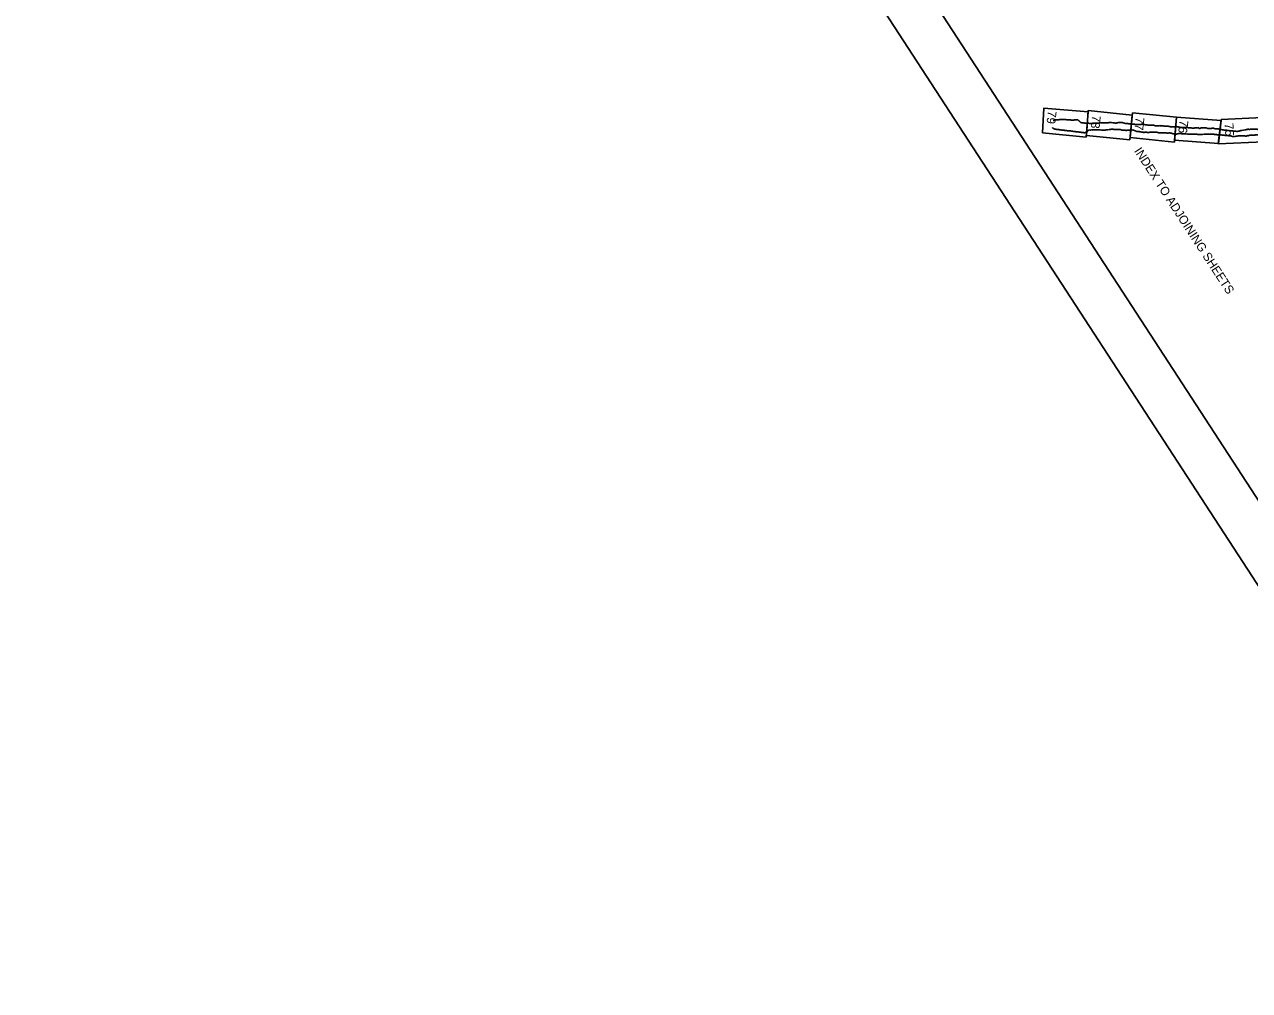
# Model space of a CAD drawing. Extents: x 3953924 to 3974542, y 193747 to 216192.
# Drawn here: x 3954169 to 3962352, y 193991 to 200444 of the extents above; entities that cross this region are included whole.
import ezdxf

# ---------------------------------------------------------------- set-up
doc = ezdxf.new("R2010")
doc.units = 0
for name, color, linetype in [('G-ANNO-NPLT', 7, 'Continuous'), ('V-ANNO-NPLT', 7, 'Continuous'), ('V-ANNO-SYMB', 7, 'Continuous')]:
    doc.layers.add(name, color=color, linetype=linetype)

msp = doc.modelspace()

# ---------------------------------------------------------------- linework, layer by layer
at = {"layer": 'G-ANNO-NPLT'}
msp.add_lwpolyline([(3954168.8, 209355.9), (3964170.5, 193991), (3974297.3, 200583), (3964295.6, 215947.9)], close=True, dxfattribs=at)
at = {"layer": 'V-ANNO-NPLT'}
msp.add_line((3961273.8, 199859.7), (3961261.8, 199692.1), dxfattribs=at)
for points in [[(3961273.8, 199859.7), (3960979.2, 199885.4), (3960970, 199720.3), (3961261.8, 199692.1)], [(3961568.2, 199838.9), (3961274.4, 199869.1), (3961262.6, 199703.3)], [(3961568.2, 199838.9), (3961553.6, 199673.4)], [(3961569.6, 199854.8), (3961555.1, 199689.7), (3961850.9, 199658.3)], [(3961865.6, 199824.2), (3961569.6, 199854.8)], [(3961850.9, 199658.3), (3961865.6, 199824.2)], [(3961865.6, 199824.2), (3961852, 199671.2)], [(3961865.6, 199824.2), (3962162.6, 199802.9)], [(3962163.5, 199810.2), (3962143.7, 199645.8), (3962448.5, 199660.1)], [(3962162.6, 199802.9), (3962144.2, 199649.7)], [(3962440.7, 199823.2), (3962163.5, 199810.2)], [(3961262.6, 199703.3), (3961553.6, 199673.4)], [(3961852, 199671.2), (3962144.2, 199649.7)]]:
    msp.add_lwpolyline(points, dxfattribs=at)
for points in [[(3961096.7, 199809.1), (3961085.3, 199808.5), (3961078.5, 199807.9), (3961071.7, 199807.5), (3961065.3, 199807.3), (3961059.1, 199806.8), (3961053.9, 199806.7), (3961052.5, 199806), (3961049.8, 199804.6), (3961045.7, 199802.6), (3961044.5, 199802), (3961043.2, 199802.1), (3961041.5, 199802.7)], [(3961149.7, 199806.4), (3961137.4, 199807.6), (3961124.6, 199808.3), (3961114.5, 199808.5), (3961106.8, 199809.1), (3961099.1, 199809.6), (3961096.7, 199809.1)], [(3961210.2, 199803.1), (3961205.6, 199806.2), (3961203.1, 199807), (3961197.3, 199806.6), (3961189.8, 199806.1), (3961183.1, 199805.9), (3961176.5, 199805.4), (3961171.3, 199805.2), (3961165.1, 199805.5), (3961155.8, 199806), (3961149.7, 199806.4)], [(3961268.1, 199784.4), (3961264.2, 199784.6), (3961258.9, 199785), (3961255.2, 199785.4), (3961250.7, 199785.6), (3961245.3, 199786.4), (3961238, 199787.1), (3961232.3, 199787.7), (3961228.4, 199788.2), (3961224.8, 199788.5), (3961220, 199793), (3961216.3, 199796.9), (3961213.7, 199799.8), (3961210.2, 199803.1)], [(3961289.4, 199783), (3961284.4, 199783.2), (3961279.6, 199783.7), (3961268.1, 199784.4)], [(3961430.7, 199788.8), (3961419, 199789.5), (3961407.3, 199787.3), (3961403.3, 199786.8), (3961391.6, 199787), (3961380.6, 199786.9), (3961369.7, 199787.2), (3961362.4, 199787.4), (3961357.5, 199788.3), (3961352.5, 199786.8), (3961329.4, 199785), (3961310.5, 199782.5), (3961300.4, 199781.9), (3961295.6, 199782.5), (3961289.4, 199783)], [(3961553, 199780.5), (3961539.9, 199781.5), (3961529.3, 199782.2), (3961522.7, 199783), (3961515.3, 199784.9), (3961500.9, 199789), (3961493.3, 199788.7), (3961482.2, 199789.5), (3961471, 199787.8), (3961461.7, 199785.7), (3961447.8, 199786.4), (3961430.7, 199788.8)], [(3961633.1, 199777.7), (3961626.8, 199776.6), (3961619.2, 199776.4), (3961610.6, 199776.3), (3961597.8, 199776.5), (3961575.1, 199778.2), (3961563, 199779.2), (3961552.8, 199780.6)], [(3961858.8, 199761.9), (3961850.7, 199761), (3961842.9, 199759.5), (3961835.1, 199760), (3961825, 199761.1), (3961814.2, 199763.2), (3961807.4, 199764.3), (3961788.8, 199764.8), (3961775.8, 199766.2), (3961762.3, 199767.2), (3961752.9, 199768.1), (3961744.8, 199767.1), (3961734, 199767), (3961722.5, 199768), (3961713.5, 199770.5), (3961701.3, 199771.6), (3961684.9, 199770.8), (3961681, 199771.7), (3961678.1, 199772), (3961666.2, 199772.6), (3961656.5, 199774), (3961643.7, 199776.2), (3961633.1, 199777.7)], [(3962002.3, 199752.9), (3961987, 199752.6), (3961976.1, 199751.9), (3961963.5, 199753), (3961950.7, 199753.2), (3961938.3, 199755.1), (3961918.9, 199756.3), (3961912.1, 199756.5), (3961902.6, 199755.1), (3961892, 199756.6), (3961880.1, 199758.9), (3961869.1, 199760.9), (3961858.8, 199761.9)], [(3961082.5, 199741.2), (3961074.9, 199742), (3961067.2, 199743), (3961060.2, 199743.9), (3961056, 199744.7), (3961050.8, 199745.5), (3961045.6, 199748), (3961040.5, 199750.6), (3961036.1, 199753.6), (3961033.3, 199755.9)], [(3961145.2, 199733.2), (3961135.3, 199734.5), (3961123, 199736.2), (3961114.6, 199737.3), (3961104.6, 199738.3), (3961092.4, 199739.9), (3961082.5, 199741.2)], [(3961213.8, 199725.4), (3961203.7, 199726.5), (3961197.1, 199727.2), (3961188.1, 199728.5), (3961179.7, 199729.2), (3961174.8, 199730), (3961168.3, 199730.8), (3961156.6, 199732.4), (3961147.8, 199733.1), (3961145.2, 199733.2)], [(3961264, 199727.2), (3961259.4, 199724.5), (3961254.7, 199721.8), (3961252, 199721), (3961244, 199721.6), (3961237.4, 199722.2), (3961228.9, 199723.4), (3961221.9, 199724.3), (3961214.4, 199725.2), (3961213.8, 199725.4)], [(3961316.6, 199740.1), (3961306.4, 199739.6), (3961299.8, 199739), (3961295, 199739.2), (3961288.6, 199738.8), (3961285.6, 199739.2), (3961264, 199727.2)], [(3961434.5, 199744.2), (3961423.7, 199743.3), (3961405.2, 199740), (3961394, 199739.4), (3961380.3, 199737.9), (3961363.7, 199739), (3961344.2, 199740.3), (3961335, 199740.5), (3961324.9, 199740.1), (3961316.6, 199740.1)], [(3961561.3, 199738.9), (3961547.7, 199737.8), (3961542.6, 199737.4), (3961536.7, 199738.3), (3961531.5, 199736.2), (3961522.1, 199738.1), (3961502.9, 199737.5), (3961494.9, 199739.9), (3961479.7, 199742.6), (3961453, 199742.7), (3961448.3, 199743), (3961442.2, 199743.7), (3961434.5, 199744.2)], [(3961555.2, 199691.8), (3961555.5, 199691.4), (3961555.6, 199690.7), (3961555.7, 199690.3), (3961555.7, 199689.7)], [(3961628, 199725.8), (3961626.9, 199726.1), (3961619.2, 199727.4), (3961610, 199729), (3961605.6, 199729.5), (3961601, 199729), (3961594.2, 199731.3), (3961590, 199732.8), (3961587.7, 199734.6), (3961581.1, 199736.6), (3961576.8, 199737.6), (3961569.9, 199739.4), (3961561.3, 199738.9)], [(3961628, 199725.8), (3961634.8, 199724.5), (3961642.1, 199723.5), (3961649.3, 199723.3), (3961657.8, 199723.9)], [(3961671.4, 199723.2), (3961664.1, 199723.6), (3961657.8, 199723.9)], [(3961855.7, 199712.5), (3961841.4, 199713.2), (3961820.9, 199720), (3961808.1, 199718.8), (3961795.4, 199719.6), (3961784, 199720.6), (3961766.8, 199720), (3961757.8, 199719.1), (3961745, 199721.2), (3961732.7, 199723.7), (3961719.7, 199725), (3961703.7, 199724.5), (3961691.3, 199724.8), (3961680.3, 199723.1), (3961671.4, 199723.2)], [(3962060.1, 199711.6), (3962049.3, 199710.4), (3962029.2, 199709.9), (3962018.1, 199709.7), (3962006.8, 199710), (3961982.8, 199711.4), (3961963.3, 199710.4), (3961951.1, 199710.9), (3961938.8, 199711.5), (3961917.5, 199714.5), (3961907.7, 199713.6), (3961900, 199714), (3961892.5, 199715.2), (3961886.5, 199715.2), (3961874.4, 199714.4), (3961865.2, 199712.3), (3961855.7, 199712.5)], [(3962034.3, 199752.9), (3962025.4, 199752.4), (3962023.2, 199750.3), (3962022.1, 199749.8), (3962019.5, 199749.5), (3962017.4, 199749.3), (3962015.6, 199749.4), (3962015.1, 199749.8), (3962014.5, 199752.6), (3962014, 199753.1), (3962008.6, 199752.5), (3962002.5, 199752.7)], [(3962108.9, 199750.9), (3962103.2, 199750.4), (3962092.9, 199749.6), (3962085.5, 199749.1), (3962077.4, 199749.7), (3962072.1, 199749.9), (3962067.1, 199751.4), (3962063.2, 199753.6), (3962059.6, 199754.4), (3962055.9, 199753.7), (3962047.3, 199753.4), (3962041.9, 199752.7), (3962038.5, 199752.8), (3962034.3, 199752.9)], [(3962188.8, 199703.1), (3962178.2, 199704.4), (3962170.8, 199705.4), (3962165.5, 199705.7), (3962156, 199706.9), (3962144.8, 199707.6), (3962136, 199707.8), (3962127.1, 199708.9), (3962121, 199708.7), (3962114.4, 199710.2), (3962109.4, 199711.7), (3962101.6, 199710.9), (3962094.2, 199711.4), (3962086.3, 199711.6), (3962079.7, 199711.5), (3962070.7, 199712), (3962066.6, 199712.1), (3962060.1, 199711.6)], [(3962108.9, 199750.9), (3962115.2, 199750), (3962119.1, 199748.4), (3962124.1, 199747), (3962129.5, 199746.8)], [(3962164.5, 199742.5), (3962151.1, 199744.4), (3962142.9, 199746), (3962133.9, 199746.5), (3962129.5, 199746.8)], [(3962301.5, 199736), (3962294, 199735.2), (3962286.6, 199732.6), (3962280.4, 199732), (3962273.2, 199730.4), (3962268.9, 199729.4), (3962262.9, 199731), (3962259.8, 199731.5), (3962248.4, 199731.3), (3962238.2, 199732.4), (3962233.1, 199733.3), (3962226.4, 199733.6), (3962217.5, 199734.6), (3962212, 199735.6), (3962199.5, 199737.2), (3962195.7, 199737.3), (3962192.1, 199738.4), (3962185.2, 199737.7), (3962178.2, 199739.1), (3962169, 199741.2), (3962164.5, 199742.5)], [(3962315.3, 199700.5), (3962306.5, 199700), (3962297.2, 199699.9), (3962289.2, 199699.4), (3962283.6, 199699.2), (3962275.5, 199699), (3962265.1, 199697.9), (3962260.9, 199696.9), (3962255.7, 199696.5), (3962250.2, 199696.8), (3962242.7, 199695.7), (3962239.9, 199695.6), (3962235.5, 199696.6), (3962231.7, 199697.5), (3962228.9, 199699.4), (3962222.9, 199699.8), (3962218.2, 199700.1), (3962209.9, 199701.5), (3962205.8, 199702.2), (3962201.3, 199701.5), (3962194.2, 199702.3), (3962188.8, 199703.1)], [(3962444.5, 199739.3), (3962428.7, 199741), (3962415, 199742.8), (3962402.9, 199743.9), (3962391.1, 199745.2), (3962377, 199745.1), (3962366.6, 199745.2), (3962355.7, 199744.3), (3962352.3, 199742.8), (3962345.8, 199743.6), (3962341.8, 199743.8), (3962332.4, 199742.3), (3962321.3, 199739.2), (3962301.5, 199736)], [(3962469.2, 199697.1), (3962461.6, 199698.9), (3962456.2, 199700.4), (3962448.3, 199700.9), (3962434.5, 199703.7), (3962423.4, 199703.3), (3962413.6, 199705.9), (3962406.1, 199705.6), (3962401.3, 199706.4), (3962397.9, 199706.5), (3962387.6, 199705.5), (3962378.5, 199705.2), (3962369.3, 199704.3), (3962360.8, 199703.9), (3962353.3, 199703.6), (3962346.9, 199701.8), (3962341.8, 199700.2), (3962339.2, 199701.9), (3962337.1, 199701.7), (3962334, 199699.7), (3962315.3, 199700.5)]]:
    msp.add_spline(points, degree=3, dxfattribs=at)
at = {"layer": 'V-ANNO-SYMB'}
msp.add_lwpolyline([(3955180.9, 208373.9), (3964205.1, 194510.7), (3973808.1, 200761.7), (3964783.9, 214624.9), (3955180.9, 208373.9)], dxfattribs=at)

# ---------------------------------------------------------------- texts
at = {"layer": 'V-ANNO-NPLT'}
for s, height, rotation, p in [('79', 58.5, 263.77382, (3961005.6, 199869.4)), ('78', 58.5, 263.77382, (3961300.9, 199838.9)), ('77', 58.5, 263.77382, (3961592.5, 199827.1)), ('76', 58.5, 262.77382, (3961886.5, 199807.1)), ('75', 58.5, 273.77383, (3962185.9, 199783.1)), ('INDEX TO ADJOINING SHEETS', 58.33, 303.06191, (3961578.9, 199599.2))]:
    msp.add_text(s, height=height, rotation=rotation, dxfattribs=at).set_placement(p)

doc.saveas('drawing.dxf')
